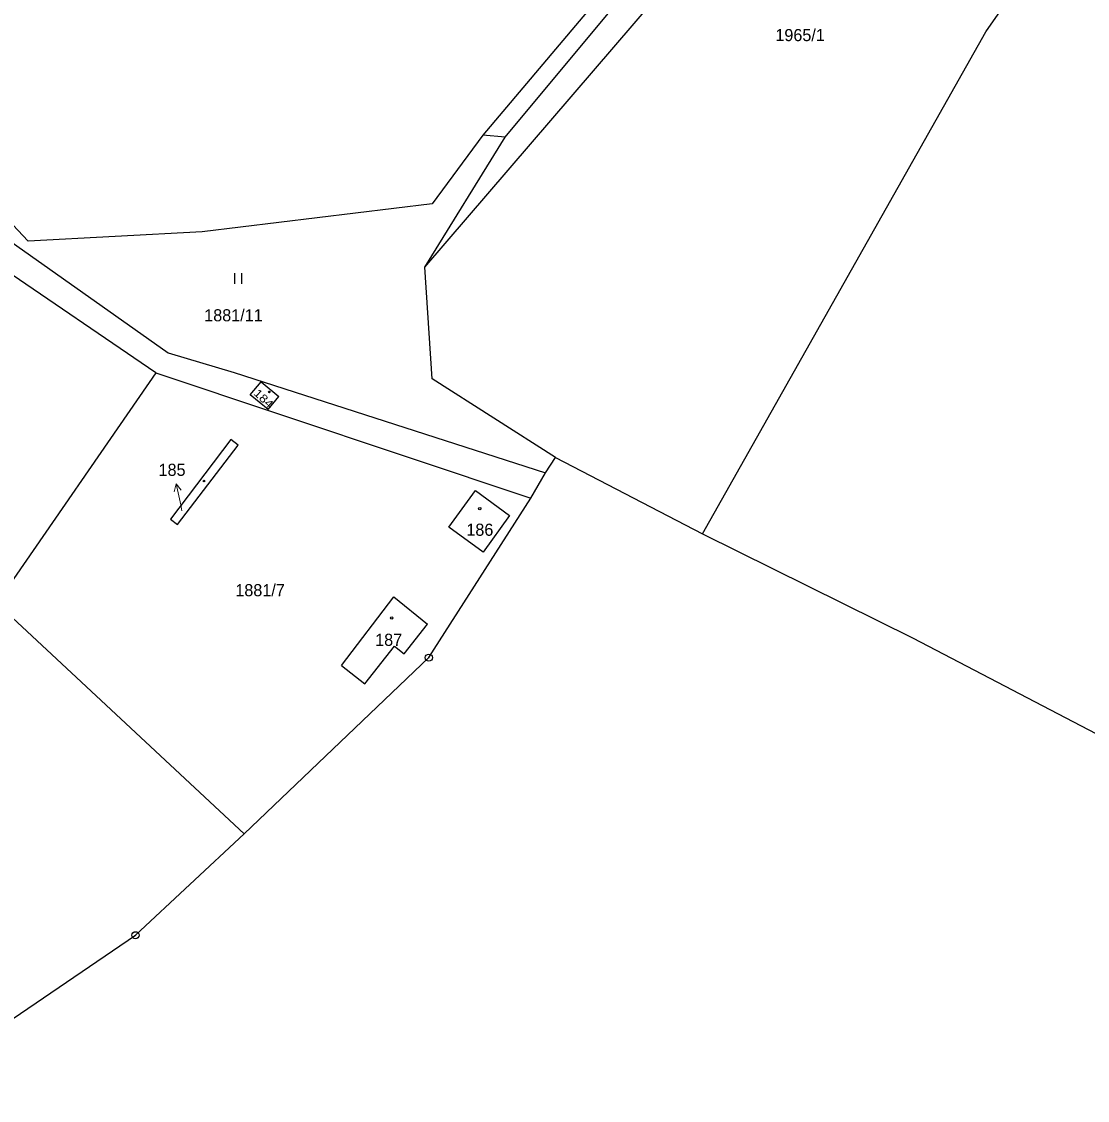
# Model space of a CAD drawing. Extents: x -820420 to -815896, y -1105820 to -1103643.
# Drawn here: x -817970.2 to -817820.3, y -1105595.4 to -1105443.7 of the extents above; entities that cross this region are included whole.
import ezdxf
from ezdxf.enums import TextEntityAlignment as Align

# ---------------------------------------------------------------- set-up
doc = ezdxf.new("R2010")
doc.units = 0
doc.header["$LTSCALE"] = 0.68
for name, color, linetype, lineweight in [('1', 7, 'Continuous', 25), ('3', 7, 'Continuous', 25), ('5', 7, 'Continuous', 25), ('7', 7, 'Continuous', 13), ('8', 7, 'Continuous', 25)]:
    doc.layers.add(name, color=color, linetype=linetype, lineweight=lineweight)
doc.layers.add('2', color=7, linetype='Continuous')

msp = doc.modelspace()

# ---------------------------------------------------------------- linework, layer by layer
at = {"layer": '1'}
for p, q in [((-817834.63, -1105445.18), (-817825.59, -1105432.28)), ((-817885.84, -1105436.6), (-817905.34, -1105459.71)), ((-817913.51, -1105478.26), (-817878.93, -1105438.02)), ((-817902.19, -1105460), (-817884.31, -1105438.47)), ((-817874.44, -1105515.78), (-817834.63, -1105445.18)), ((-817994.18, -1105458.85), (-817949.57, -1105490.31)), ((-817913.51, -1105478.26), (-817902.19, -1105460)), ((-817905.34, -1105459.71), (-817912.44, -1105469.36)), ((-817902.19, -1105460), (-817905.34, -1105459.71)), ((-817951.3, -1105493.14), (-817998.06, -1105461.28)), ((-817969.25, -1105474.62), (-817981.08, -1105462.15)), ((-817912.44, -1105469.36), (-817944.78, -1105473.32)), ((-817944.78, -1105473.32), (-817969.25, -1105474.62)), ((-817912.46, -1105493.98), (-817913.51, -1105478.26)), ((-817949.57, -1105490.31), (-817940.29, -1105493.1)), ((-817951.3, -1105493.14), (-817973.69, -1105525.5)), ((-817951.3, -1105493.14), (-817898.58, -1105510.76)), ((-817940.29, -1105493.1), (-817896.53, -1105507.2)), ((-817895.13, -1105505.02), (-817912.46, -1105493.98)), ((-817938.03, -1105496.23), (-817936.5, -1105494.38)), ((-817936.5, -1105494.38), (-817934, -1105496.45)), ((-817935.54, -1105498.27), (-817938.03, -1105496.23)), ((-817935.54, -1105498.27), (-817934, -1105496.45)), ((-817940.76, -1105502.52), (-817949.27, -1105513.69)), ((-817939.75, -1105503.28), (-817940.76, -1105502.52)), ((-817948.28, -1105514.45), (-817939.75, -1105503.28)), ((-817896.53, -1105507.2), (-817895.13, -1105505.02)), ((-817895.13, -1105505.02), (-817874.44, -1105515.78)), ((-817898.58, -1105510.76), (-817896.53, -1105507.2)), ((-817912.93, -1105533.17), (-817898.58, -1105510.76)), ((-817910.12, -1105514.84), (-817906.39, -1105509.69)), ((-817906.39, -1105509.69), (-817901.59, -1105513.17)), ((-817949.27, -1105513.69), (-817948.28, -1105514.45)), ((-817901.59, -1105513.17), (-817905.31, -1105518.32)), ((-817905.31, -1105518.32), (-817910.12, -1105514.84)), ((-817874.44, -1105515.78), (-817844.82, -1105530.45)), ((-817973.69, -1105525.5), (-817938.91, -1105557.94)), ((-817925.2, -1105534.27), (-817917.86, -1105524.63)), ((-817917.86, -1105524.63), (-817913.1, -1105528.45)), ((-817916.4, -1105532.64), (-817913.1, -1105528.45)), ((-817844.82, -1105530.45), (-817816.97, -1105544.94)), ((-817921.91, -1105536.86), (-817917.74, -1105531.58)), ((-817917.74, -1105531.58), (-817916.4, -1105532.64)), ((-817912.93, -1105533.17), (-817938.91, -1105557.94)), ((-817925.2, -1105534.27), (-817921.91, -1105536.86)), ((-817954.18, -1105572.2), (-817938.91, -1105557.94)), ((-817988.28, -1105595.42), (-817954.18, -1105572.2))]:
    msp.add_line(p, q, dxfattribs=at)
at = {"layer": '3'}
for p, q in [((-817940.211, -1105480.61), (-817940.211, -1105479.11)), ((-817939.21, -1105480.61), (-817939.21, -1105479.11))]:
    msp.add_line(p, q, dxfattribs=at)
at = {"layer": '5'}
for centre, radius in [((-817935.3546, -1105495.8094), 0.1172), ((-817944.5446, -1105508.3394), 0.1172), ((-817905.7668, -1105512.2292), 0.175), ((-817918.1468, -1105527.5892), 0.175)]:
    msp.add_circle(centre, radius, dxfattribs=at)
at = {"layer": '7'}
msp.add_line((-817948.434, -1105508.755), (-817948.716, -1105509.838), dxfattribs=at)
msp.add_lwpolyline([(-817947.64, -1105512.51), (-817947.81, -1105511.69), (-817948.434, -1105508.755), (-817947.736, -1105509.63)], dxfattribs=at)
at = {"layer": '8'}
for centre, radius in [((-817912.93, -1105533.1699), 0.5), ((-817912.93, -1105533.1699), 0.0303), ((-817954.18, -1105572.1999), 0.5), ((-817954.18, -1105572.1999), 0.0303)]:
    msp.add_circle(centre, radius, dxfattribs=at)

# ---------------------------------------------------------------- texts
at = {"layer": '2'}
for s, p in [('1965/1', (-817860.73, -1105446.495)), ('1881/11', (-817940.399, -1105485.885)), ('186', (-817905.759, -1105516.035)), ('1881/7', (-817936.66, -1105524.535)), ('187', (-817918.579, -1105531.515))]:
    msp.add_text(s, height=1.7, dxfattribs=at).set_placement(p, align=Align.CENTER)
at = {"layer": '2', "width": 1.2}
msp.add_text('184', height=1.14, rotation=317, dxfattribs=at).set_placement((-817936.5457, -1105497.1523), align=Align.CENTER)
at = {"layer": '2'}
msp.add_text('185', height=1.7, dxfattribs=at).set_placement((-817947.139, -1105507.615), align=Align.RIGHT)

doc.saveas('drawing.dxf')
